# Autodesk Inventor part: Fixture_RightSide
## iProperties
Shininess: 64.0
Length Units: 11269
Angle Units: 11279
Time Units: 11290
Mass Units: 11286
Length Display Precision: 3
Angle Display Precision: 2
Compacted: True
Part Number: Fixture_RightSide
Document SubType Name: Modeling
Created: 2003-06
Designer: Administrator
Manufacturer: Standard
Standards Organization: Custom
Density: 1 g/cm^3
Density: 0.0
Volumn: 0.0
Area: 0.0
PropertySet Name: Model Information
Control State: 0
Master: False
Checked Out: False
Author: Administrator
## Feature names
1. Extrusion1
2. Extrusion2
3. Hole1
